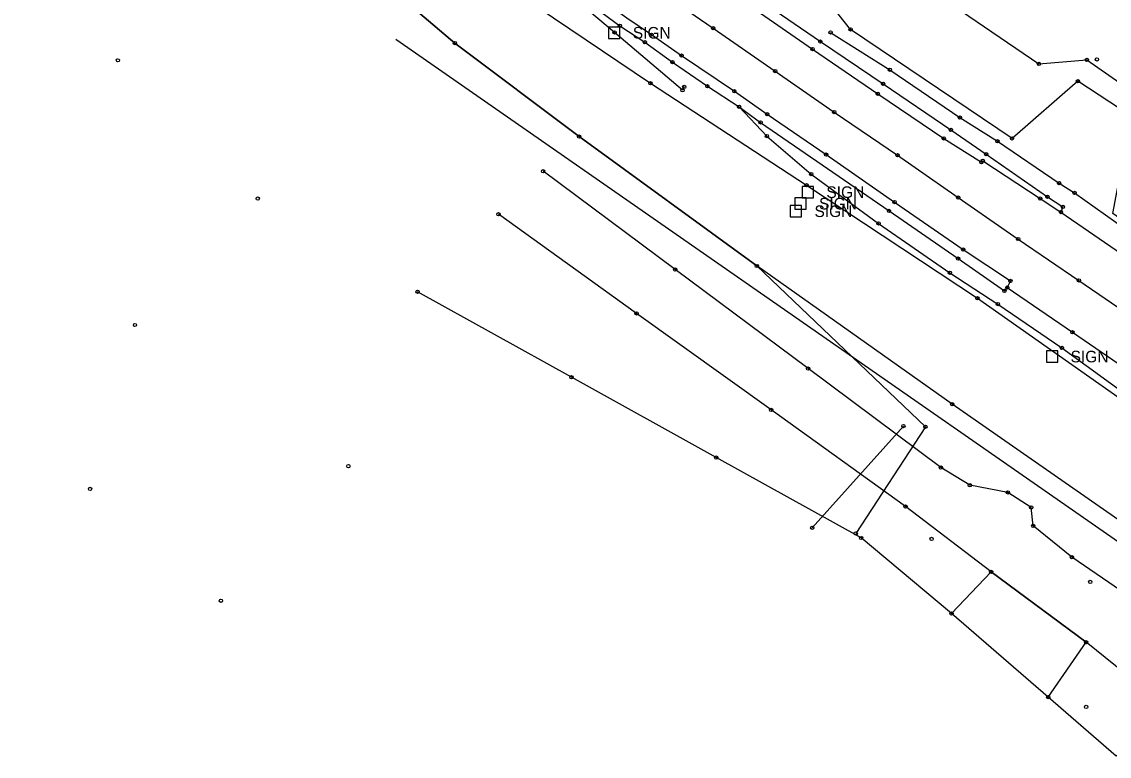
# Model space of a CAD drawing. Extents: x 15502398 to 15534190, y 8766930 to 8782112.
# Drawn here: x 15514814.8 to 15515143.1, y 8778822.8 to 8779044.6 of the extents above; entities that cross this region are included whole.
import ezdxf

# ---------------------------------------------------------------- set-up
doc = ezdxf.new("R2010")
doc.units = 0
for name, color, linetype in [('Default', 7, 'Continuous'), ('EXT_BL', 7, 'Continuous'), ('EXT_C', 7, 'Continuous'), ('EXT_D', 7, 'Continuous'), ('EXT_EG', 7, 'Continuous'), ('EXT_EP', 7, 'Continuous'), ('EXT_SH', 7, 'Continuous'), ('EXT_SNP', 7, 'Continuous'), ('Fence', 7, 'Continuous'), ('Natural', 7, 'Continuous'), ('SurPointsNonDTM', 7, 'Continuous'), ('SurRoadPoints', 7, 'Continuous'), ('SurSurveyPoints', 7, 'Continuous')]:
    doc.layers.add(name, color=color, linetype=linetype)

msp = doc.modelspace()

# ---------------------------------------------------------------- linework, layer by layer
at = {"layer": 'Default'}
msp.add_lwpolyline([(15515014.78, 8779024.91), (15515014.27, 8779023.91), (15514993.78, 8779041.38), (15514983.04, 8779050.29), (15514963.22, 8779065.38), (15514949.32, 8779075.04)], dxfattribs=at)
at = {"layer": 'EXT_BL'}
for points in [[(15514972.37, 8779103.34), (15514965.29, 8779104.12), (15514949.73, 8779114.8), (15514960.51, 8779127.28), (15514971.69, 8779129.58), (15515012.98, 8779104.1), (15515039.09, 8779087.26), (15515084.34, 8779057.54), (15515121.87, 8779031.85), (15515136.34, 8779033.05), (15515158.53, 8779017.54), (15515157.87, 8778999.81), (15515198.39, 8778971.5), (15515237.86, 8778943.51), (15515264.4, 8778926.3), (15515290.1, 8778939.84)], [(15515299.76, 8778934.56), (15515270.88, 8778905.09), (15515228.44, 8778928.8), (15515189.45, 8778954.86), (15515144.22, 8778986.67), (15515149.73, 8779016.04), (15515133.63, 8779026.63), (15515113.74, 8779009.34), (15515065.03, 8779042.26), (15515052.77, 8779057.78), (15515036.39, 8779065.61), (15515003.2, 8779083.25), (15514972.37, 8779103.34)], [(15515236.34, 8778829.26), (15515147, 8778893.37), (15515095.71, 8778929.07), (15515036.69, 8778970.82), (15514983.06, 8779009.89), (15514945.58, 8779038.12), (15514929.61, 8779051.74), (15514918.26, 8779072.09), (15514924.14, 8779086.4)], [(15514924.14, 8779086.4), (15514944.89, 8779074.69), (15514948.37, 8779068.62), (15514949.86, 8779067.79), (15514955.86, 8779058.94), (15515004.6, 8779026.01), (15515051.74, 8778995.2), (15515103.32, 8778961.08), (15515168.39, 8778915.34), (15515228.98, 8778873.25), (15515256.8, 8778852.96)], [(15515182.28, 8778848.25), (15515148.4, 8778871.52), (15515131.84, 8778882.87), (15515120.14, 8778892.33), (15515119.53, 8778897.92), (15515112.5, 8778902.46), (15515101.01, 8778904.62), (15515092.27, 8778909.96), (15515052.18, 8778939.84), (15515012.09, 8778969.72), (15514972.2, 8778999.45)], [(15515162.24, 8778836.22), (15515136.09, 8778857.21), (15515107.41, 8778878.44), (15515081.62, 8778898.18), (15515041, 8778927.34), (15515000.39, 8778956.51), (15514958.68, 8778986.46)], [(15515236.34, 8778829.26), (15515226.47, 8778826.26), (15515206, 8778842.2), (15515182.28, 8778848.25), (15515162.24, 8778836.22), (15515145.2, 8778822.76), (15515124.7, 8778840.65), (15515095.48, 8778865.85), (15515068.16, 8778888.68), (15515024.46, 8778912.95), (15514980.75, 8778937.23), (15514934.3, 8778963.03)]]:
    msp.add_lwpolyline(points, dxfattribs=at)
at = {"layer": 'EXT_C'}
msp.add_lwpolyline([(15514955.43, 8779089.67), (15514965.34, 8779083.38), (15514972.98, 8779078.29), (15514981.11, 8779072.17), (15514988.29, 8779067.21), (15514995.56, 8779062.44), (15514996.44, 8779061.55), (15515003.11, 8779056.73), (15515023.53, 8779042.6), (15515042.26, 8779029.68), (15515060.1, 8779017.29), (15515079.18, 8779004.26), (15515097.5, 8778991.5), (15515115.64, 8778978.97), (15515133.93, 8778966.45), (15515153.59, 8778952.94), (15515173.34, 8778939.62), (15515192.18, 8778926.74), (15515210.55, 8778914.23), (15515226.89, 8778902.88), (15515245.57, 8778890.09), (15515263, 8778878.15)], dxfattribs=at)
at = {"layer": 'EXT_D'}
msp.add_line((15515197.28, 8778851.57), (15514927.71, 8779039.18), dxfattribs=at)
at = {"layer": 'EXT_EG'}
msp.add_line((15515124.7, 8778840.65), (15515136.09, 8778857.21), dxfattribs=at)
msp.add_lwpolyline([(15515124.7, 8778840.65), (15515095.48, 8778865.85), (15515107.41, 8778878.44), (15515136.09, 8778857.21)], dxfattribs=at)
at = {"layer": 'EXT_EP'}
for points in [[(15515004, 8779071.19), (15515021.39, 8779058.52), (15515036.5, 8779048.12), (15515053.54, 8779036.32), (15515073.21, 8779022.82), (15515093.16, 8779009.36), (15515104.5, 8779002.14), (15515104.91, 8779002.59), (15515122.29, 8778991.19), (15515128.53, 8778987.1), (15515146.83, 8778974.46), (15515164.62, 8778962.4), (15515181.23, 8778950.95), (15515199.54, 8778938.45), (15515218.74, 8778925.26), (15515238.6, 8778911.77), (15515263.66, 8778894.48), (15515280.51, 8778882.85)], [(15514989.57, 8779051.49), (15514997.49, 8779045.8), (15515004.92, 8779040.68), (15515013.98, 8779034.36), (15515029.92, 8779023.61), (15515039.85, 8779016.64), (15515057.6, 8779004.48), (15515078.3, 8778990.12), (15515099.03, 8778975.76), (15515113.27, 8778966.3), (15515112.33, 8778964.28), (15515131.99, 8778950.83), (15515154.7, 8778935.27), (15515175.1, 8778921.33), (15515195.6, 8778907.33), (15515215.71, 8778893.41), (15515237.55, 8778878.49), (15515258.35, 8778864.15)]]:
    msp.add_lwpolyline(points, dxfattribs=at)
at = {"layer": 'EXT_SH'}
for points in [[(15514980.52, 8779091.29), (15514980.66, 8779090.37), (15514989.32, 8779084.51), (15514995.93, 8779079.81), (15515001.88, 8779075.54), (15515004.96, 8779073.56), (15515023.67, 8779061.07), (15515038.1, 8779050.82), (15515055.88, 8779038.59), (15515074.84, 8779025.86), (15515095.29, 8779011.9), (15515105.95, 8779004.56), (15515124.43, 8778991.74), (15515129.13, 8778988.68), (15515128.53, 8778987.1)], [(15514962.8, 8779065.26), (15514979.3, 8779054.28), (15514986.62, 8779049.75), (15514988.14, 8779048.72), (15514995.38, 8779043.37), (15515002.91, 8779038.39), (15515011.24, 8779032.4), (15515021.77, 8779025.08), (15515031.37, 8779018.91), (15515037.86, 8779014.18), (15515076.61, 8778987.47), (15515097.47, 8778973.05), (15515111.46, 8778963.29), (15515112.33, 8778964.28)]]:
    msp.add_lwpolyline(points, dxfattribs=at)
at = {"layer": 'EXT_SNP'}
for points in [[(15515058.99, 8779041.35), (15515076.89, 8779030.08), (15515098.01, 8779015.66), (15515109.36, 8779008.51), (15515127.95, 8778995.86), (15515132.65, 8778992.91), (15515151.28, 8778979.64), (15515167.98, 8778968), (15515185.66, 8778956.55), (15515196.8, 8778948.4), (15515223.42, 8778930.68), (15515242.55, 8778917.64), (15515262.08, 8778907.53), (15515284.46, 8778895.27)], [(15515031.37, 8779018.91), (15515039.75, 8779010.04), (15515053.15, 8778998.57), (15515073.46, 8778983.69), (15515095.02, 8778968.8), (15515109.51, 8778959.31), (15515128.81, 8778946.07), (15515150.83, 8778930.1), (15515171.77, 8778916.42), (15515191.15, 8778901.74), (15515211.68, 8778887.62), (15515233.22, 8778872.61), (15515253.77, 8778858.06)]]:
    msp.add_lwpolyline(points, dxfattribs=at)
at = {"layer": 'Fence'}
msp.add_lwpolyline([(15515080.98, 8778922.46), (15515053.44, 8778891.78)], dxfattribs=at)
at = {"layer": 'Natural'}
msp.add_lwpolyline([(15514714.5, 8779119.23), (15514742.47, 8779138.72), (15514734.07, 8779166.12), (15514775.23, 8779152.76), (15514828.83, 8779114.63), (15514870.83, 8779086.34), (15514918.03, 8779051.7), (15514929.61, 8779051.74), (15514945.58, 8779038.12), (15514983.06, 8779009.89), (15515036.69, 8778970.82), (15515087.59, 8778922.26), (15515066.58, 8778890.05)], dxfattribs=at)
at = {"layer": 'SurPointsNonDTM'}
for centre in [(15514993.78, 8779041.38), (15514945.58, 8779038.12), (15515014.27, 8779023.91), (15515014.78, 8779024.91), (15514983.06, 8779009.89), (15515036.69, 8778970.82), (15515080.98, 8778922.46), (15515087.59, 8778922.26), (15515053.44, 8778891.78), (15515066.58, 8778890.05)]:
    msp.add_circle(centre, 0.5, dxfattribs=at)
at = {"layer": 'SurRoadPoints'}
for points in [[(15514993.68, 8779039.54), (15514993.68, 8779039.54), (15514995.39, 8779039.54), (15514995.39, 8779042.96), (15514991.96, 8779042.96), (15514991.96, 8779039.54), (15514993.68, 8779039.54)], [(15515052.11, 8778991.41), (15515052.11, 8778991.41), (15515053.82, 8778991.41), (15515053.82, 8778994.83), (15515050.39, 8778994.83), (15515050.39, 8778991.41), (15515052.11, 8778991.41)], [(15515049.88, 8778987.94), (15515049.88, 8778987.94), (15515051.59, 8778987.94), (15515051.59, 8778991.36), (15515048.17, 8778991.36), (15515048.17, 8778987.94), (15515049.88, 8778987.94)], [(15515048.51, 8778985.65), (15515048.51, 8778985.65), (15515050.22, 8778985.65), (15515050.22, 8778989.08), (15515046.79, 8778989.08), (15515046.79, 8778985.65), (15515048.5, 8778985.65)], [(15515125.82, 8778941.76), (15515125.82, 8778941.76), (15515127.53, 8778941.76), (15515127.53, 8778945.18), (15515124.11, 8778945.18), (15515124.11, 8778941.76), (15515125.82, 8778941.76)]]:
    msp.add_lwpolyline(points, dxfattribs=at)
at = {"layer": 'SurSurveyPoints'}
for centre in [(15514995.38, 8779043.37), (15515004.92, 8779040.68), (15515023.53, 8779042.6), (15515058.99, 8779041.35), (15515065.03, 8779042.26), (15514945.58, 8779038.12), (15515002.91, 8779038.39), (15515055.88, 8779038.59), (15515013.98, 8779034.36), (15515053.54, 8779036.32), (15514843.84, 8779032.93), (15515011.24, 8779032.4), (15515076.89, 8779030.08), (15515121.87, 8779031.85), (15515136.34, 8779033.05), (15515139.36, 8779033.2), (15515042.26, 8779029.68), (15515004.6, 8779026.01), (15515021.77, 8779025.08), (15515029.92, 8779023.61), (15515074.84, 8779025.86), (15515133.63, 8779026.63), (15515073.21, 8779022.82), (15515031.37, 8779018.91), (15515031.37, 8779018.91), (15515060.1, 8779017.29), (15515037.86, 8779014.18), (15515039.85, 8779016.64), (15515098.01, 8779015.66), (15515095.29, 8779011.9), (15514983.06, 8779009.89), (15515039.75, 8779010.04), (15515093.16, 8779009.36), (15515109.36, 8779008.51), (15515113.74, 8779009.34), (15515057.6, 8779004.48), (15515079.18, 8779004.26), (15515105.95, 8779004.56), (15515104.5, 8779002.14), (15515104.91, 8779002.59), (15514972.2, 8778999.45), (15515053.15, 8778998.57), (15515051.74, 8778995.2), (15515127.95, 8778995.86), (15514886.04, 8778991.16), (15515097.5, 8778991.5), (15515122.29, 8778991.19), (15515124.43, 8778991.74), (15515132.65, 8778992.91), (15515076.61, 8778987.47), (15515078.3, 8778990.12), (15515129.13, 8778988.68), (15514958.68, 8778986.46), (15515128.53, 8778987.1), (15515128.53, 8778987.1), (15515073.46, 8778983.69), (15515115.64, 8778978.97), (15515099.03, 8778975.76), (15515097.47, 8778973.05), (15515012.09, 8778969.72), (15515036.69, 8778970.82), (15515095.02, 8778968.8), (15515113.27, 8778966.3), (15515133.93, 8778966.45), (15514934.3, 8778963.03), (15514934.3, 8778963.03), (15515103.32, 8778961.08), (15515111.46, 8778963.29), (15515112.33, 8778964.28), (15515112.33, 8778964.28), (15515109.51, 8778959.31), (15515000.39, 8778956.51), (15514848.99, 8778953), (15515131.99, 8778950.83), (15515128.81, 8778946.07), (15515052.18, 8778939.84), (15514980.75, 8778937.23), (15515095.71, 8778929.07), (15515041, 8778927.34), (15515024.46, 8778912.95), (15514913.43, 8778910.37), (15515092.27, 8778909.96), (15514835.44, 8778903.52), (15515101.01, 8778904.62), (15515112.5, 8778902.46), (15515081.62, 8778898.18), (15515119.53, 8778897.92), (15515120.14, 8778892.33), (15515068.16, 8778888.68), (15515089.45, 8778888.38), (15515131.84, 8778882.87), (15515107.41, 8778878.44), (15515107.41, 8778878.44), (15515137.38, 8778875.43), (15514874.93, 8778869.73), (15515095.48, 8778865.85), (15515095.48, 8778865.85), (15515136.09, 8778857.21), (15515136.09, 8778857.21), (15515124.7, 8778840.65), (15515124.7, 8778840.65), (15515136.13, 8778837.65)]:
    msp.add_circle(centre, 0.5, dxfattribs=at)

# ---------------------------------------------------------------- texts
at = {"layer": 'SurRoadPoints'}
for p in [(15514999.28, 8779039.5), (15515057.71, 8778991.37), (15515055.49, 8778987.9), (15515054.11, 8778985.61), (15515131.43, 8778941.72)]:
    msp.add_text('SIGN', height=3.498, dxfattribs=at).set_placement(p)

doc.saveas('drawing.dxf')
